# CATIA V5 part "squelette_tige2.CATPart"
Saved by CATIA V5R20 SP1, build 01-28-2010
Part number: squelette_tige2
Publications: "Droite.4", "Droite.5", "Plan.3"
Bounding box of the stored display mesh (mm): x 11.269 to 2412094, y 111.357 to 8263428.5, z -94.223 to 5089073
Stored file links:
  C:\Users\Fox\Desktop\IAO Projet\A RENDRE\Sauvegarde IFMA\squelette_tige2.CATPart
  C:\Users\Fox\Desktop\IAO Projet\A RENDRE\Sauvegarde IFMA\squelette.CATProduct
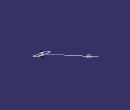
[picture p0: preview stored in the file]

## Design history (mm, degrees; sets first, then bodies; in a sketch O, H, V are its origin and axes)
Set1
  Line1: type PtPt, FirstPoint Point1, SecondPoint Point4
  Line2: type Normal, RefPoint Point1, RefSkin Plane2, Start -10, End 10
  Plane1: type Normal, Curve Line2, RefPoint Point1
Set2
  Point1: linked copy from another document
  Plane2: linked copy from another document
  Point2: linked copy from another document
  Line3: linked copy from another document
  Point3: linked copy from another document
  Point4: linked copy from another document
Body1 (main body)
